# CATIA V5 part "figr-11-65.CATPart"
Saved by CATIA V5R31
Part number: Part1
Bounding box of the stored display mesh (mm): x -54 to 54, y -91.936 to 93.838, z -12.649 to 110.643
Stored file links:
  D:\PROJECTS\Project 2021\US EDITION\CATIA V5 6R 2021\Resources\Part Files\c11_catia_v5_6r2021_prt\figr-11-65.CATPart
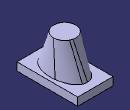
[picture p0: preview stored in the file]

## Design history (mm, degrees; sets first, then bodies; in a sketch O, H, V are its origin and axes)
Set1
  Loft1: Sections (Sketch4; Sketch3)
Body1 (main body)
  Sketch1 on yz-plane, origin (0, 0, 0), H (0, 1, 0), V (0, 0, 1)
    point P1 (93.8379, 11.643)
    line L1 (93.8379, 11.643) -> (93.8379, -12.6487)
    line L2 (93.8379, -12.6487) -> (-91.9362, -12.6487)
    line L3 (-91.9362, -12.6487) -> (-91.9362, 11.643)
    line L4 (-91.9362, 11.643) -> (93.8379, 11.643)
    point P5 (93.8379, 11.643)
    vertical: L1 V, L3 V
    horizontal: L2 H, L4 H
    coincidence: P5 P1
  Pad1: profile Sketch1, direction (1, 0, 0), length 54, mirrored extent
  Sketch2 on face of Pad1, origin (0, 0, 11.643), H (1, 0, 0), V (0, 1, 0)
    circle A1 centre (0, 0) radius 16.7533
    point P1 (16.7533, 0)
    coincidence: A1 P1, P1 H
  Pad2: profile Sketch2, direction (0, 0, 1), length 99
  SewSurface1: SewingRemoveFace face of Pad2, SplitPlane Loft1
  Sketch3 on face of Pad2, origin (0, 0, 110.643), H (1, 0, 0), V (0, 1, 0)
    point P1 (0, 42.8937)
    point P2 (33.9651, 0)
    projected circle E1 centre (0, 0) radius 16.7533 from edge [face of Pad2 | face of Pad2]
    circle A1 centre (0, 0) radius 33.9651
    point P3 (0, 33.9651)
    coincidence: P1 V, P2 H, A1 P2, A1 P3, P3 V
  Sketch4 on face of Pad1, origin (0, 0, 11.643), H (1, 0, 0), V (0, 1, 0)
    ellipse A1 centre (0, 0) semi-axes 69.9141, 43.1918 rotation 90
    point P1 (0, 69.9141)
    point P2 (43.1918, 0)
    coincidence: P1 V, P2 H, A1 P1, A1 P2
